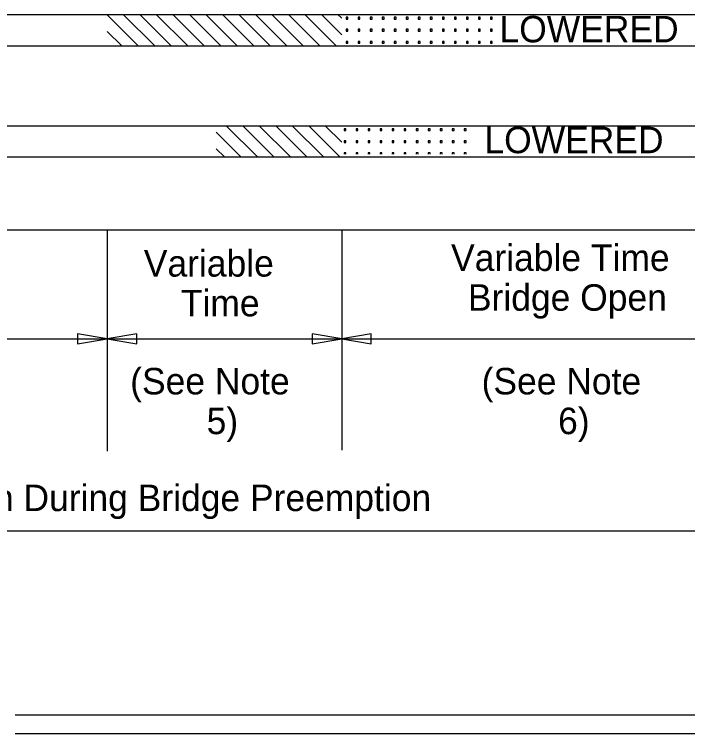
# Model space of a CAD drawing. Extents: x 15 to 764, y 7 to 487.
# Drawn here: x 581.3 to 670.2, y 29.1 to 124.1 of the extents above; entities that cross this region are included whole.
import ezdxf

# ---------------------------------------------------------------- set-up
doc = ezdxf.new("R2010")
doc.units = 0
for name, color, linetype in [('Default', 7, 'Continuous'), ('Dimension', 7, 'Continuous'), ('TextStructures', 7, 'Continuous')]:
    doc.layers.add(name, color=color, linetype=linetype)

msp = doc.modelspace()

# ---------------------------------------------------------------- linework, layer by layer
at = {"layer": 'Default'}
for p, q in [((462.687, 124.052), (756.61, 124.052)), ((593.572, 123.989), (597.668, 119.905)), ((595.691, 124.052), (599.851, 119.905)), ((597.874, 124.052), (602.034, 119.905)), ((600.057, 124.052), (604.217, 119.905)), ((593.572, 121.812), (595.485, 119.905)), ((462.687, 119.905), (756.61, 119.905)), ((462.687, 109.343), (756.61, 109.343)), ((609.293, 109.343), (613.422, 105.216)), ((607.965, 108.491), (611.242, 105.216)), ((607.965, 106.311), (609.061, 105.216)), ((462.687, 95.608), (756.61, 95.608)), ((593.572, 95.608), (593.572, 66.354)), ((624.556, 95.608), (624.556, 66.488)), ((542.459, 81.197), (593.572, 81.197)), ((593.572, 81.197), (624.556, 81.197)), ((624.556, 81.197), (689.177, 81.197)), ((495.877, 55.858), (720.584, 55.858))]:
    msp.add_line(p, q, dxfattribs=at)
for points in [[(602.241, 124.052), (606.4, 119.905)], [(604.428, 124.052), (608.578, 119.905)], [(606.607, 124.052), (610.755, 119.905)], [(608.787, 124.052), (612.935, 119.905)], [(610.965, 124.052), (615.112, 119.905)], [(613.141, 124.052), (617.292, 119.905)], [(615.321, 124.052), (619.472, 119.905)], [(617.498, 124.052), (621.648, 119.905)], [(619.678, 124.052), (623.825, 119.905)], [(621.857, 124.052), (624.556, 121.354)], [(624.035, 124.052), (624.556, 123.531)], [(625.378, 123.429), (625.378, 123.668), (625.139, 123.667), (625.139, 123.429), (625.378, 123.429)], [(625.378, 123.429), (625.378, 123.668), (625.139, 123.667), (625.139, 123.429), (625.378, 123.429)], [(626.964, 123.429), (626.964, 123.668), (626.725, 123.667), (626.725, 123.429), (626.964, 123.429)], [(626.964, 123.429), (626.964, 123.668), (626.725, 123.667), (626.725, 123.429), (626.964, 123.429)], [(628.554, 123.429), (628.554, 123.668), (628.315, 123.667), (628.315, 123.429), (628.554, 123.429)], [(628.554, 123.429), (628.554, 123.668), (628.315, 123.667), (628.315, 123.429), (628.554, 123.429)], [(630.14, 123.429), (630.14, 123.668), (629.901, 123.667), (629.901, 123.429), (630.14, 123.429)], [(630.14, 123.429), (630.14, 123.668), (629.901, 123.667), (629.901, 123.429), (630.14, 123.429)], [(631.73, 123.429), (631.73, 123.668), (631.491, 123.667), (631.491, 123.429), (631.73, 123.429)], [(631.73, 123.429), (631.73, 123.668), (631.491, 123.667), (631.491, 123.429), (631.73, 123.429)], [(633.317, 123.429), (633.317, 123.668), (633.078, 123.667), (633.078, 123.429), (633.317, 123.429)], [(633.317, 123.429), (633.317, 123.668), (633.078, 123.667), (633.078, 123.429), (633.317, 123.429)], [(634.906, 123.429), (634.906, 123.668), (634.667, 123.667), (634.667, 123.429), (634.906, 123.429)], [(634.906, 123.429), (634.906, 123.668), (634.667, 123.667), (634.667, 123.429), (634.906, 123.429)], [(636.493, 123.429), (636.493, 123.668), (636.254, 123.667), (636.254, 123.429), (636.493, 123.429)], [(636.493, 123.429), (636.493, 123.668), (636.254, 123.667), (636.254, 123.429), (636.493, 123.429)], [(638.082, 123.429), (638.082, 123.668), (637.844, 123.667), (637.844, 123.429), (638.082, 123.429)], [(638.082, 123.429), (638.082, 123.668), (637.844, 123.667), (637.844, 123.429), (638.082, 123.429)], [(639.669, 123.429), (639.669, 123.668), (639.43, 123.667), (639.43, 123.429), (639.669, 123.429)], [(639.669, 123.429), (639.669, 123.668), (639.43, 123.667), (639.43, 123.429), (639.669, 123.429)], [(641.259, 123.429), (641.259, 123.668), (641.02, 123.667), (641.02, 123.429), (641.259, 123.429)], [(641.259, 123.429), (641.259, 123.668), (641.02, 123.667), (641.02, 123.429), (641.259, 123.429)], [(642.845, 123.429), (642.845, 123.668), (642.606, 123.667), (642.606, 123.429), (642.845, 123.429)], [(642.845, 123.429), (642.845, 123.668), (642.606, 123.667), (642.606, 123.429), (642.845, 123.429)], [(644.435, 123.429), (644.435, 123.668), (644.196, 123.667), (644.196, 123.429), (644.435, 123.429)], [(644.435, 123.429), (644.435, 123.668), (644.196, 123.667), (644.196, 123.429), (644.435, 123.429)], [(625.378, 121.842), (625.378, 122.081), (625.139, 122.08), (625.139, 121.842), (625.378, 121.842)], [(625.378, 121.842), (625.378, 122.081), (625.139, 122.08), (625.139, 121.842), (625.378, 121.842)], [(626.964, 121.842), (626.964, 122.081), (626.725, 122.08), (626.725, 121.842), (626.964, 121.842)], [(626.964, 121.842), (626.964, 122.081), (626.725, 122.08), (626.725, 121.842), (626.964, 121.842)], [(628.554, 121.842), (628.554, 122.081), (628.315, 122.08), (628.315, 121.842), (628.554, 121.842)], [(628.554, 121.842), (628.554, 122.081), (628.315, 122.08), (628.315, 121.842), (628.554, 121.842)], [(630.14, 121.842), (630.14, 122.081), (629.901, 122.08), (629.901, 121.842), (630.14, 121.842)], [(630.14, 121.842), (630.14, 122.081), (629.901, 122.08), (629.901, 121.842), (630.14, 121.842)], [(631.73, 121.842), (631.73, 122.081), (631.491, 122.08), (631.491, 121.842), (631.73, 121.842)], [(631.73, 121.842), (631.73, 122.081), (631.491, 122.08), (631.491, 121.842), (631.73, 121.842)], [(633.317, 121.842), (633.317, 122.081), (633.078, 122.08), (633.078, 121.842), (633.317, 121.842)], [(633.317, 121.842), (633.317, 122.081), (633.078, 122.08), (633.078, 121.842), (633.317, 121.842)], [(634.906, 121.842), (634.906, 122.081), (634.667, 122.08), (634.667, 121.842), (634.906, 121.842)], [(634.906, 121.842), (634.906, 122.081), (634.667, 122.08), (634.667, 121.842), (634.906, 121.842)], [(636.493, 121.842), (636.493, 122.081), (636.254, 122.08), (636.254, 121.842), (636.493, 121.842)], [(636.493, 121.842), (636.493, 122.081), (636.254, 122.08), (636.254, 121.842), (636.493, 121.842)], [(638.082, 121.842), (638.082, 122.081), (637.844, 122.08), (637.844, 121.842), (638.082, 121.842)], [(638.082, 121.842), (638.082, 122.081), (637.844, 122.08), (637.844, 121.842), (638.082, 121.842)], [(639.669, 121.842), (639.669, 122.081), (639.43, 122.08), (639.43, 121.842), (639.669, 121.842)], [(639.669, 121.842), (639.669, 122.081), (639.43, 122.08), (639.43, 121.842), (639.669, 121.842)], [(641.259, 121.842), (641.259, 122.081), (641.02, 122.08), (641.02, 121.842), (641.259, 121.842)], [(641.259, 121.842), (641.259, 122.081), (641.02, 122.08), (641.02, 121.842), (641.259, 121.842)], [(642.845, 121.842), (642.845, 122.081), (642.606, 122.08), (642.606, 121.842), (642.845, 121.842)], [(642.845, 121.842), (642.845, 122.081), (642.606, 122.08), (642.606, 121.842), (642.845, 121.842)], [(644.435, 121.842), (644.435, 122.081), (644.196, 122.08), (644.196, 121.842), (644.435, 121.842)], [(644.435, 121.842), (644.435, 122.081), (644.196, 122.08), (644.196, 121.842), (644.435, 121.842)], [(625.378, 120.253), (625.378, 120.492), (625.139, 120.491), (625.139, 120.253), (625.378, 120.253)], [(625.378, 120.253), (625.378, 120.492), (625.139, 120.491), (625.139, 120.253), (625.378, 120.253)], [(626.964, 120.253), (626.964, 120.492), (626.725, 120.491), (626.725, 120.253), (626.964, 120.253)], [(626.964, 120.253), (626.964, 120.492), (626.725, 120.491), (626.725, 120.253), (626.964, 120.253)], [(628.554, 120.253), (628.554, 120.492), (628.315, 120.491), (628.315, 120.253), (628.554, 120.253)], [(628.554, 120.253), (628.554, 120.492), (628.315, 120.491), (628.315, 120.253), (628.554, 120.253)], [(630.14, 120.253), (630.14, 120.492), (629.901, 120.491), (629.901, 120.253), (630.14, 120.253)], [(630.14, 120.253), (630.14, 120.492), (629.901, 120.491), (629.901, 120.253), (630.14, 120.253)], [(631.73, 120.253), (631.73, 120.492), (631.491, 120.491), (631.491, 120.253), (631.73, 120.253)], [(631.73, 120.253), (631.73, 120.492), (631.491, 120.491), (631.491, 120.253), (631.73, 120.253)], [(633.317, 120.253), (633.317, 120.492), (633.078, 120.491), (633.078, 120.253), (633.317, 120.253)], [(633.317, 120.253), (633.317, 120.492), (633.078, 120.491), (633.078, 120.253), (633.317, 120.253)], [(634.906, 120.253), (634.906, 120.492), (634.667, 120.491), (634.667, 120.253), (634.906, 120.253)], [(634.906, 120.253), (634.906, 120.492), (634.667, 120.491), (634.667, 120.253), (634.906, 120.253)], [(636.493, 120.253), (636.493, 120.492), (636.254, 120.491), (636.254, 120.253), (636.493, 120.253)], [(636.493, 120.253), (636.493, 120.492), (636.254, 120.491), (636.254, 120.253), (636.493, 120.253)], [(638.082, 120.253), (638.082, 120.492), (637.844, 120.491), (637.844, 120.253), (638.082, 120.253)], [(638.082, 120.253), (638.082, 120.492), (637.844, 120.491), (637.844, 120.253), (638.082, 120.253)], [(639.669, 120.253), (639.669, 120.492), (639.43, 120.491), (639.43, 120.253), (639.669, 120.253)], [(639.669, 120.253), (639.669, 120.492), (639.43, 120.491), (639.43, 120.253), (639.669, 120.253)], [(641.259, 120.253), (641.259, 120.492), (641.02, 120.491), (641.02, 120.253), (641.259, 120.253)], [(641.259, 120.253), (641.259, 120.492), (641.02, 120.491), (641.02, 120.253), (641.259, 120.253)], [(642.845, 120.253), (642.845, 120.492), (642.606, 120.491), (642.606, 120.253), (642.845, 120.253)], [(642.845, 120.253), (642.845, 120.492), (642.606, 120.491), (642.606, 120.253), (642.845, 120.253)], [(644.435, 120.253), (644.435, 120.492), (644.196, 120.491), (644.196, 120.253), (644.435, 120.253)], [(644.435, 120.253), (644.435, 120.492), (644.196, 120.491), (644.196, 120.253), (644.435, 120.253)], [(611.473, 109.343), (615.602, 105.216)], [(613.655, 109.343), (617.78, 105.216)], [(615.831, 109.343), (619.96, 105.216)], [(618.011, 109.343), (622.139, 105.216)], [(620.191, 109.343), (624.317, 105.216)], [(622.368, 109.343), (624.556, 107.156)], [(624.546, 109.343), (624.556, 109.334)], [(625.098, 108.697), (625.098, 108.937), (624.861, 108.935), (624.861, 108.697), (625.098, 108.697)], [(625.098, 108.697), (625.098, 108.937), (624.861, 108.935), (624.861, 108.697), (625.098, 108.697)], [(626.686, 108.697), (626.686, 108.937), (626.449, 108.935), (626.449, 108.697), (626.686, 108.697)], [(626.686, 108.697), (626.686, 108.937), (626.449, 108.935), (626.449, 108.697), (626.686, 108.697)], [(628.274, 108.697), (628.274, 108.937), (628.038, 108.935), (628.038, 108.697), (628.274, 108.697)], [(628.274, 108.697), (628.274, 108.937), (628.038, 108.935), (628.038, 108.697), (628.274, 108.697)], [(629.862, 108.697), (629.862, 108.937), (629.625, 108.935), (629.625, 108.697), (629.862, 108.697)], [(629.862, 108.697), (629.862, 108.937), (629.625, 108.935), (629.625, 108.697), (629.862, 108.697)], [(631.45, 108.697), (631.45, 108.937), (631.214, 108.935), (631.214, 108.697), (631.45, 108.697)], [(631.45, 108.697), (631.45, 108.937), (631.214, 108.935), (631.214, 108.697), (631.45, 108.697)], [(633.038, 108.697), (633.038, 108.937), (632.801, 108.935), (632.801, 108.697), (633.038, 108.697)], [(633.038, 108.697), (633.038, 108.937), (632.801, 108.935), (632.801, 108.697), (633.038, 108.697)], [(634.627, 108.697), (634.627, 108.937), (634.39, 108.935), (634.39, 108.697), (634.627, 108.697)], [(634.627, 108.697), (634.627, 108.937), (634.39, 108.935), (634.39, 108.697), (634.627, 108.697)], [(636.214, 108.697), (636.214, 108.937), (635.977, 108.935), (635.977, 108.697), (636.214, 108.697)], [(636.214, 108.697), (636.214, 108.937), (635.977, 108.935), (635.977, 108.697), (636.214, 108.697)], [(637.803, 108.697), (637.803, 108.937), (637.566, 108.935), (637.566, 108.697), (637.803, 108.697)], [(637.803, 108.697), (637.803, 108.937), (637.566, 108.935), (637.566, 108.697), (637.803, 108.697)], [(639.39, 108.697), (639.39, 108.937), (639.154, 108.935), (639.154, 108.697), (639.39, 108.697)], [(639.39, 108.697), (639.39, 108.937), (639.154, 108.935), (639.154, 108.697), (639.39, 108.697)], [(640.979, 108.697), (640.979, 108.937), (640.742, 108.935), (640.742, 108.697), (640.979, 108.697)], [(640.979, 108.697), (640.979, 108.937), (640.742, 108.935), (640.742, 108.697), (640.979, 108.697)], [(625.098, 107.109), (625.098, 107.348), (624.861, 107.347), (624.861, 107.109), (625.098, 107.109)], [(625.098, 107.109), (625.098, 107.348), (624.861, 107.347), (624.861, 107.109), (625.098, 107.109)], [(626.686, 107.109), (626.686, 107.348), (626.449, 107.347), (626.449, 107.109), (626.686, 107.109)], [(626.686, 107.109), (626.686, 107.348), (626.449, 107.347), (626.449, 107.109), (626.686, 107.109)], [(628.274, 107.109), (628.274, 107.348), (628.038, 107.347), (628.038, 107.109), (628.274, 107.109)], [(628.274, 107.109), (628.274, 107.348), (628.038, 107.347), (628.038, 107.109), (628.274, 107.109)], [(629.862, 107.109), (629.862, 107.348), (629.625, 107.347), (629.625, 107.109), (629.862, 107.109)], [(629.862, 107.109), (629.862, 107.348), (629.625, 107.347), (629.625, 107.109), (629.862, 107.109)], [(631.45, 107.109), (631.45, 107.348), (631.214, 107.347), (631.214, 107.109), (631.45, 107.109)], [(631.45, 107.109), (631.45, 107.348), (631.214, 107.347), (631.214, 107.109), (631.45, 107.109)], [(633.038, 107.109), (633.038, 107.348), (632.801, 107.347), (632.801, 107.109), (633.038, 107.109)], [(633.038, 107.109), (633.038, 107.348), (632.801, 107.347), (632.801, 107.109), (633.038, 107.109)], [(634.627, 107.109), (634.627, 107.348), (634.39, 107.347), (634.39, 107.109), (634.627, 107.109)], [(634.627, 107.109), (634.627, 107.348), (634.39, 107.347), (634.39, 107.109), (634.627, 107.109)], [(636.214, 107.109), (636.214, 107.348), (635.977, 107.347), (635.977, 107.109), (636.214, 107.109)], [(636.214, 107.109), (636.214, 107.348), (635.977, 107.347), (635.977, 107.109), (636.214, 107.109)], [(637.803, 107.109), (637.803, 107.348), (637.566, 107.347), (637.566, 107.109), (637.803, 107.109)], [(637.803, 107.109), (637.803, 107.348), (637.566, 107.347), (637.566, 107.109), (637.803, 107.109)], [(639.39, 107.109), (639.39, 107.348), (639.154, 107.347), (639.154, 107.109), (639.39, 107.109)], [(639.39, 107.109), (639.39, 107.348), (639.154, 107.347), (639.154, 107.109), (639.39, 107.109)], [(640.979, 107.109), (640.979, 107.348), (640.742, 107.347), (640.742, 107.109), (640.979, 107.109)], [(640.979, 107.109), (640.979, 107.348), (640.742, 107.347), (640.742, 107.109), (640.979, 107.109)], [(625.098, 105.761), (624.861, 105.758)], [(624.861, 105.758), (624.861, 105.595)], [(625.098, 105.595), (625.098, 105.761)], [(626.686, 105.761), (626.449, 105.758)], [(626.449, 105.758), (626.449, 105.595)], [(626.686, 105.595), (626.686, 105.761)], [(628.274, 105.761), (628.038, 105.758)], [(628.038, 105.758), (628.038, 105.595)], [(628.274, 105.595), (628.274, 105.761)], [(629.862, 105.761), (629.625, 105.758)], [(629.625, 105.758), (629.625, 105.595)], [(629.862, 105.595), (629.862, 105.761)], [(631.45, 105.761), (631.214, 105.758)], [(631.214, 105.758), (631.214, 105.595)], [(631.45, 105.595), (631.45, 105.761)], [(633.038, 105.761), (632.801, 105.758)], [(632.801, 105.758), (632.801, 105.595)], [(633.038, 105.595), (633.038, 105.761)], [(634.627, 105.761), (634.39, 105.758)], [(634.39, 105.758), (634.39, 105.595)], [(634.627, 105.595), (634.627, 105.761)], [(636.214, 105.761), (635.977, 105.758)], [(635.977, 105.758), (635.977, 105.595)], [(636.214, 105.595), (636.214, 105.761)], [(637.803, 105.761), (637.566, 105.758)], [(637.566, 105.758), (637.566, 105.595)], [(637.803, 105.595), (637.803, 105.761)], [(639.39, 105.761), (639.154, 105.758)], [(639.154, 105.758), (639.154, 105.595)], [(639.39, 105.595), (639.39, 105.761)], [(640.979, 105.761), (640.742, 105.758)], [(640.742, 105.758), (640.742, 105.595)], [(640.979, 105.595), (640.979, 105.761)], [(613.234, 105.406), (613.423, 105.216)]]:
    msp.add_lwpolyline(points, dxfattribs=at)
at = {"layer": 'Dimension'}
for points in [[(593.572, 81.197), (589.668, 81.859), (589.668, 80.536)], [(593.572, 81.197), (597.477, 80.536), (597.477, 81.859)], [(624.556, 81.197), (620.651, 81.859), (620.651, 80.536)], [(624.556, 81.197), (628.461, 80.536), (628.461, 81.859)]]:
    msp.add_lwpolyline(points, close=True, dxfattribs=at)
at = {"layer": 'TextStructures'}
for p, q in [((462.687, 105.216), (756.61, 105.216)), ((581.413, 31.553), (756.61, 31.553)), ((581.413, 29.053), (756.61, 29.053))]:
    msp.add_line(p, q, dxfattribs=at)

# ---------------------------------------------------------------- texts
for p in [(645.394, 120.357), (643.4, 105.717)]:
    msp.add_text('LOWERED', height=3.5, rotation=0.00072, dxfattribs=at).set_placement(p)
for s, p in [('Variable', (598.409, 89.418)), ('Variable Time', (638.995, 90.16)), (' Bridge Open', (639.922, 84.91)), (' Time', (601.998, 84.168)), ('(See Note', (596.607, 73.857)), ('(See Note ', (643.032, 73.857)), ('5)', (606.706, 68.607)), ('6)', (653.132, 68.607)), ('Operation During Bridge Preemption', (560.658, 58.444))]:
    msp.add_text(s, height=3.5, dxfattribs=at).set_placement(p)

doc.saveas('drawing.dxf')
